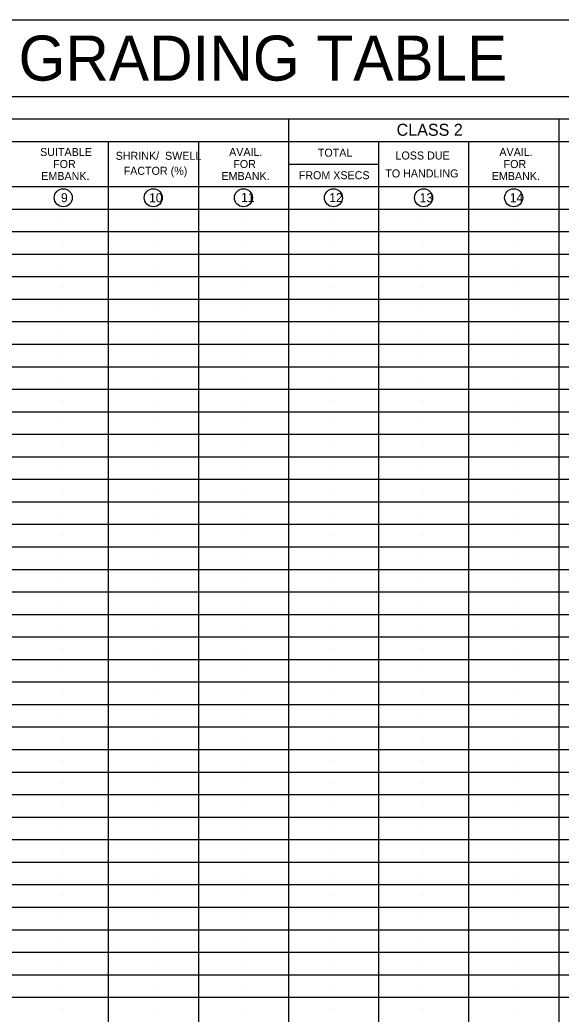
# Model space of a CAD drawing. Extents: x 1.3 to 38.6, y 0 to 21.1.
# Drawn here: x 9.92 to 15.32, y 11.12 to 21.05 of the extents above; entities that cross this region are included whole.
import ezdxf

# ---------------------------------------------------------------- set-up
doc = ezdxf.new("R2010")
doc.units = 0
for name, color, linetype in [('CONS-LOGO', 7, 'Continuous'), ('TTLB-TEXT', 7, 'Continuous'), ('USER-LINE', 7, 'Continuous')]:
    doc.layers.add(name, color=color, linetype=linetype)

msp = doc.modelspace()

# ---------------------------------------------------------------- linework, layer by layer
at = {"layer": 'CONS-LOGO'}
for centre in [(10.3479, 19.278), (11.2479, 19.278), (12.1479, 19.278), (13.0479, 19.278), (13.9479, 19.278), (14.8479, 19.278)]:
    msp.add_circle(centre, 0.09, dxfattribs=at)
at = {"layer": 'TTLB-TEXT'}
for p, q in [((2.248, 21.055), (22.498, 21.055)), ((2.248, 20.29), (22.498, 20.29)), ((2.698, 20.065), (17.098, 20.065)), ((12.598, 20.0651), (12.598, 4.54)), ((15.298, 20.0651), (15.298, 4.54)), ((2.698, 19.84), (22.498, 19.84)), ((10.798, 19.8401), (10.798, 4.54)), ((11.698, 19.8401), (11.698, 4.54)), ((13.498, 19.8401), (13.498, 4.54)), ((14.398, 19.8401), (14.398, 4.54)), ((12.598, 19.615), (13.498, 19.615)), ((2.698, 19.39), (22.498, 19.39)), ((2.248, 19.165), (22.498, 19.165)), ((2.698, 18.94), (22.498, 18.94)), ((2.698, 18.715), (22.498, 18.715)), ((2.698, 18.49), (22.498, 18.49)), ((2.698, 18.265), (22.498, 18.265)), ((2.698, 18.04), (22.498, 18.04)), ((2.698, 17.815), (22.498, 17.815)), ((2.698, 17.59), (22.498, 17.59)), ((2.698, 17.365), (22.498, 17.365)), ((2.698, 17.14), (22.498, 17.14)), ((2.698, 16.915), (22.498, 16.915)), ((2.698, 16.69), (22.498, 16.69)), ((2.698, 16.465), (22.498, 16.465)), ((2.698, 16.24), (22.498, 16.24)), ((2.698, 16.015), (22.498, 16.015)), ((2.698, 15.79), (22.498, 15.79)), ((2.698, 15.565), (22.498, 15.565)), ((2.698, 15.34), (22.498, 15.34)), ((2.698, 15.115), (22.498, 15.115)), ((2.698, 14.89), (22.498, 14.89)), ((2.698, 14.665), (22.498, 14.665)), ((2.698, 14.44), (22.498, 14.44)), ((2.698, 14.215), (22.498, 14.215)), ((2.698, 13.99), (22.498, 13.99)), ((2.698, 13.765), (22.498, 13.765)), ((2.698, 13.54), (22.498, 13.54)), ((2.698, 13.315), (22.498, 13.315)), ((2.698, 13.09), (22.498, 13.09)), ((2.698, 12.865), (22.498, 12.865)), ((2.698, 12.64), (22.498, 12.64)), ((2.698, 12.415), (22.498, 12.415)), ((2.698, 12.19), (22.498, 12.19)), ((2.698, 11.965), (22.498, 11.965)), ((2.698, 11.74), (22.498, 11.74)), ((2.698, 11.515), (22.498, 11.515)), ((2.698, 11.29), (22.498, 11.29))]:
    msp.add_line(p, q, dxfattribs=at)
at = {"layer": 'USER-LINE'}
for p, q in [((10.348, 19.2775), (10.348, 19.2775)), ((11.248, 19.2775), (11.248, 19.2775)), ((12.148, 19.2775), (12.148, 19.2775)), ((13.048, 19.2775), (13.048, 19.2775)), ((13.948, 19.2775), (13.948, 19.2775)), ((14.848, 19.2775), (14.848, 19.2775)), ((10.348, 19.0525), (10.348, 19.0525)), ((11.248, 19.0525), (11.248, 19.0525)), ((12.148, 19.0525), (12.148, 19.0525)), ((13.048, 19.0525), (13.048, 19.0525)), ((13.948, 19.0525), (13.948, 19.0525)), ((14.848, 19.0525), (14.848, 19.0525)), ((10.348, 18.8275), (10.348, 18.8275)), ((11.248, 18.8275), (11.248, 18.8275)), ((12.148, 18.8275), (12.148, 18.8275)), ((13.048, 18.8275), (13.048, 18.8275)), ((13.948, 18.8275), (13.948, 18.8275)), ((14.848, 18.8275), (14.848, 18.8275)), ((10.348, 18.6025), (10.348, 18.6025)), ((11.248, 18.6025), (11.248, 18.6025)), ((12.148, 18.6025), (12.148, 18.6025)), ((13.048, 18.6025), (13.048, 18.6025)), ((13.948, 18.6025), (13.948, 18.6025)), ((14.848, 18.6025), (14.848, 18.6025)), ((10.348, 18.3775), (10.348, 18.3775)), ((11.248, 18.3775), (11.248, 18.3775)), ((12.148, 18.3775), (12.148, 18.3775)), ((13.048, 18.3775), (13.048, 18.3775)), ((13.948, 18.3775), (13.948, 18.3775)), ((14.848, 18.3775), (14.848, 18.3775)), ((10.348, 18.1525), (10.348, 18.1525)), ((11.248, 18.1525), (11.248, 18.1525)), ((12.148, 18.1525), (12.148, 18.1525)), ((13.048, 18.1525), (13.048, 18.1525)), ((13.948, 18.1525), (13.948, 18.1525)), ((14.848, 18.1525), (14.848, 18.1525)), ((10.348, 17.9275), (10.348, 17.9275)), ((11.248, 17.9275), (11.248, 17.9275)), ((12.148, 17.9275), (12.148, 17.9275)), ((13.048, 17.9275), (13.048, 17.9275)), ((13.948, 17.9275), (13.948, 17.9275)), ((14.848, 17.9275), (14.848, 17.9275)), ((10.348, 17.7025), (10.348, 17.7025)), ((11.248, 17.7025), (11.248, 17.7025)), ((12.148, 17.7025), (12.148, 17.7025)), ((13.048, 17.7025), (13.048, 17.7025)), ((13.948, 17.7025), (13.948, 17.7025)), ((14.848, 17.7025), (14.848, 17.7025)), ((10.348, 17.4775), (10.348, 17.4775)), ((11.248, 17.4775), (11.248, 17.4775)), ((12.148, 17.4775), (12.148, 17.4775)), ((13.048, 17.4775), (13.048, 17.4775)), ((13.948, 17.4775), (13.948, 17.4775)), ((14.848, 17.4775), (14.848, 17.4775)), ((10.348, 17.2525), (10.348, 17.2525)), ((11.248, 17.2525), (11.248, 17.2525)), ((12.148, 17.2525), (12.148, 17.2525)), ((13.048, 17.2525), (13.048, 17.2525)), ((13.948, 17.2525), (13.948, 17.2525)), ((14.848, 17.2525), (14.848, 17.2525)), ((10.348, 17.0275), (10.348, 17.0275)), ((11.248, 17.0275), (11.248, 17.0275)), ((12.148, 17.0275), (12.148, 17.0275)), ((13.048, 17.0275), (13.048, 17.0275)), ((13.948, 17.0275), (13.948, 17.0275)), ((14.848, 17.0275), (14.848, 17.0275)), ((10.348, 16.8025), (10.348, 16.8025)), ((11.248, 16.8025), (11.248, 16.8025)), ((12.148, 16.8025), (12.148, 16.8025)), ((13.048, 16.8025), (13.048, 16.8025)), ((13.948, 16.8025), (13.948, 16.8025)), ((14.848, 16.8025), (14.848, 16.8025)), ((10.348, 16.5775), (10.348, 16.5775)), ((11.248, 16.5775), (11.248, 16.5775)), ((12.148, 16.5775), (12.148, 16.5775)), ((13.048, 16.5775), (13.048, 16.5775)), ((13.948, 16.5775), (13.948, 16.5775)), ((14.848, 16.5775), (14.848, 16.5775)), ((10.348, 16.3525), (10.348, 16.3525)), ((11.248, 16.3525), (11.248, 16.3525)), ((12.148, 16.3525), (12.148, 16.3525)), ((13.048, 16.3525), (13.048, 16.3525)), ((13.948, 16.3525), (13.948, 16.3525)), ((14.848, 16.3525), (14.848, 16.3525)), ((10.348, 16.1275), (10.348, 16.1275)), ((11.248, 16.1275), (11.248, 16.1275)), ((12.148, 16.1275), (12.148, 16.1275)), ((13.048, 16.1275), (13.048, 16.1275)), ((13.948, 16.1275), (13.948, 16.1275)), ((14.848, 16.1275), (14.848, 16.1275)), ((10.348, 15.9025), (10.348, 15.9025)), ((11.248, 15.9025), (11.248, 15.9025)), ((12.148, 15.9025), (12.148, 15.9025)), ((13.048, 15.9025), (13.048, 15.9025)), ((13.948, 15.9025), (13.948, 15.9025)), ((14.848, 15.9025), (14.848, 15.9025)), ((10.348, 15.6775), (10.348, 15.6775)), ((11.248, 15.6775), (11.248, 15.6775)), ((12.148, 15.6775), (12.148, 15.6775)), ((13.048, 15.6775), (13.048, 15.6775)), ((13.948, 15.6775), (13.948, 15.6775)), ((14.848, 15.6775), (14.848, 15.6775)), ((10.348, 15.4525), (10.348, 15.4525)), ((11.248, 15.4525), (11.248, 15.4525)), ((12.148, 15.4525), (12.148, 15.4525)), ((13.048, 15.4525), (13.048, 15.4525)), ((13.948, 15.4525), (13.948, 15.4525)), ((14.848, 15.4525), (14.848, 15.4525)), ((10.348, 15.2275), (10.348, 15.2275)), ((11.248, 15.2275), (11.248, 15.2275)), ((12.148, 15.2275), (12.148, 15.2275)), ((13.048, 15.2275), (13.048, 15.2275)), ((13.948, 15.2275), (13.948, 15.2275)), ((14.848, 15.2275), (14.848, 15.2275)), ((10.348, 15.0025), (10.348, 15.0025)), ((11.248, 15.0025), (11.248, 15.0025)), ((12.148, 15.0025), (12.148, 15.0025)), ((13.048, 15.0025), (13.048, 15.0025)), ((13.948, 15.0025), (13.948, 15.0025)), ((14.848, 15.0025), (14.848, 15.0025)), ((10.348, 14.7775), (10.348, 14.7775)), ((11.248, 14.7775), (11.248, 14.7775)), ((12.148, 14.7775), (12.148, 14.7775)), ((13.048, 14.7775), (13.048, 14.7775)), ((13.948, 14.7775), (13.948, 14.7775)), ((14.848, 14.7775), (14.848, 14.7775)), ((10.348, 14.5525), (10.348, 14.5525)), ((11.248, 14.5525), (11.248, 14.5525)), ((12.148, 14.5525), (12.148, 14.5525)), ((13.048, 14.5525), (13.048, 14.5525)), ((13.948, 14.5525), (13.948, 14.5525)), ((14.848, 14.5525), (14.848, 14.5525)), ((10.348, 14.3275), (10.348, 14.3275)), ((11.248, 14.3275), (11.248, 14.3275)), ((12.148, 14.3275), (12.148, 14.3275)), ((13.048, 14.3275), (13.048, 14.3275)), ((13.948, 14.3275), (13.948, 14.3275)), ((14.848, 14.3275), (14.848, 14.3275)), ((10.348, 14.1025), (10.348, 14.1025)), ((11.248, 14.1025), (11.248, 14.1025)), ((12.148, 14.1025), (12.148, 14.1025)), ((13.048, 14.1025), (13.048, 14.1025)), ((13.948, 14.1025), (13.948, 14.1025)), ((14.848, 14.1025), (14.848, 14.1025)), ((10.348, 13.8775), (10.348, 13.8775)), ((11.248, 13.8775), (11.248, 13.8775)), ((12.148, 13.8775), (12.148, 13.8775)), ((13.048, 13.8775), (13.048, 13.8775)), ((13.948, 13.8775), (13.948, 13.8775)), ((14.848, 13.8775), (14.848, 13.8775)), ((10.348, 13.6525), (10.348, 13.6525)), ((11.248, 13.6525), (11.248, 13.6525)), ((12.148, 13.6525), (12.148, 13.6525)), ((13.048, 13.6525), (13.048, 13.6525)), ((13.948, 13.6525), (13.948, 13.6525)), ((14.848, 13.6525), (14.848, 13.6525)), ((10.348, 13.4275), (10.348, 13.4275)), ((11.248, 13.4275), (11.248, 13.4275)), ((12.148, 13.4275), (12.148, 13.4275)), ((13.048, 13.4275), (13.048, 13.4275)), ((13.948, 13.4275), (13.948, 13.4275)), ((14.848, 13.4275), (14.848, 13.4275)), ((10.348, 13.2025), (10.348, 13.2025)), ((11.248, 13.2025), (11.248, 13.2025)), ((12.148, 13.2025), (12.148, 13.2025)), ((13.048, 13.2025), (13.048, 13.2025)), ((13.948, 13.2025), (13.948, 13.2025)), ((14.848, 13.2025), (14.848, 13.2025)), ((10.348, 12.9775), (10.348, 12.9775)), ((11.248, 12.9775), (11.248, 12.9775)), ((12.148, 12.9775), (12.148, 12.9775)), ((13.048, 12.9775), (13.048, 12.9775)), ((13.948, 12.9775), (13.948, 12.9775)), ((14.848, 12.9775), (14.848, 12.9775)), ((10.348, 12.7525), (10.348, 12.7525)), ((11.248, 12.7525), (11.248, 12.7525)), ((12.148, 12.7525), (12.148, 12.7525)), ((13.048, 12.7525), (13.048, 12.7525)), ((13.948, 12.7525), (13.948, 12.7525)), ((14.848, 12.7525), (14.848, 12.7525)), ((10.348, 12.5275), (10.348, 12.5275)), ((11.248, 12.5275), (11.248, 12.5275)), ((12.148, 12.5275), (12.148, 12.5275)), ((13.048, 12.5275), (13.048, 12.5275)), ((13.948, 12.5275), (13.948, 12.5275)), ((14.848, 12.5275), (14.848, 12.5275)), ((10.348, 12.3025), (10.348, 12.3025)), ((11.248, 12.3025), (11.248, 12.3025)), ((12.148, 12.3025), (12.148, 12.3025)), ((13.048, 12.3025), (13.048, 12.3025)), ((13.948, 12.3025), (13.948, 12.3025)), ((14.848, 12.3025), (14.848, 12.3025)), ((10.348, 12.0775), (10.348, 12.0775)), ((11.248, 12.0775), (11.248, 12.0775)), ((12.148, 12.0775), (12.148, 12.0775)), ((13.048, 12.0775), (13.048, 12.0775)), ((13.948, 12.0775), (13.948, 12.0775)), ((14.848, 12.0775), (14.848, 12.0775)), ((10.348, 11.8525), (10.348, 11.8525)), ((11.248, 11.8525), (11.248, 11.8525)), ((12.148, 11.8525), (12.148, 11.8525)), ((13.048, 11.8525), (13.048, 11.8525)), ((13.948, 11.8525), (13.948, 11.8525)), ((14.848, 11.8525), (14.848, 11.8525)), ((10.348, 11.6275), (10.348, 11.6275)), ((11.248, 11.6275), (11.248, 11.6275)), ((12.148, 11.6275), (12.148, 11.6275)), ((13.048, 11.6275), (13.048, 11.6275)), ((13.948, 11.6275), (13.948, 11.6275)), ((14.848, 11.6275), (14.848, 11.6275)), ((10.348, 11.4025), (10.348, 11.4025)), ((11.248, 11.4025), (11.248, 11.4025)), ((12.148, 11.4025), (12.148, 11.4025)), ((13.048, 11.4025), (13.048, 11.4025)), ((13.948, 11.4025), (13.948, 11.4025)), ((14.848, 11.4025), (14.848, 11.4025)), ((10.348, 11.1775), (10.348, 11.1775)), ((11.248, 11.1775), (11.248, 11.1775)), ((12.148, 11.1775), (12.148, 11.1775)), ((13.048, 11.1775), (13.048, 11.1775)), ((13.948, 11.1775), (13.948, 11.1775)), ((14.848, 11.1775), (14.848, 11.1775))]:
    msp.add_line(p, q, dxfattribs=at)

# ---------------------------------------------------------------- texts
at = {"layer": 'CONS-LOGO'}
for s, height, p in [('GRADING TABLE', 0.45, (9.902, 20.448)), ('CLASS 2', 0.12, (13.6789, 19.897)), ('SUITABLE', 0.08, (10.1171, 19.695)), ('AVAIL.', 0.08, (12.0054, 19.695)), ('TOTAL', 0.08, (12.8917, 19.688)), ('AVAIL.', 0.08, (14.7054, 19.695)), ('SHRINK/  SWELL', 0.08, (10.8719, 19.657)), ('LOSS DUE', 0.08, (13.6675, 19.66)), ('FOR', 0.08, (10.2472, 19.575)), ('FACTOR (%)', 0.08, (10.9515, 19.507)), ('FOR', 0.08, (12.0472, 19.575)), ('FOR', 0.08, (14.7472, 19.575)), ('EMBANK.', 0.08, (10.1289, 19.455)), ('EMBANK.', 0.08, (11.9289, 19.455)), ('FROM XSECS', 0.08, (12.7011, 19.463)), ('TO HANDLING', 0.08, (13.5652, 19.481)), ('EMBANK.', 0.08, (14.6289, 19.455)), ('9', 0.09, (10.326, 19.233)), ('10', 0.09, (11.206, 19.233)), ('11', 0.09, (12.125, 19.236)), ('12', 0.09, (13.006, 19.234)), ('13', 0.09, (13.909, 19.233)), ('14', 0.09, (14.809, 19.233))]:
    msp.add_text(s, height=height, dxfattribs=at).set_placement(p)

doc.saveas('drawing.dxf')
